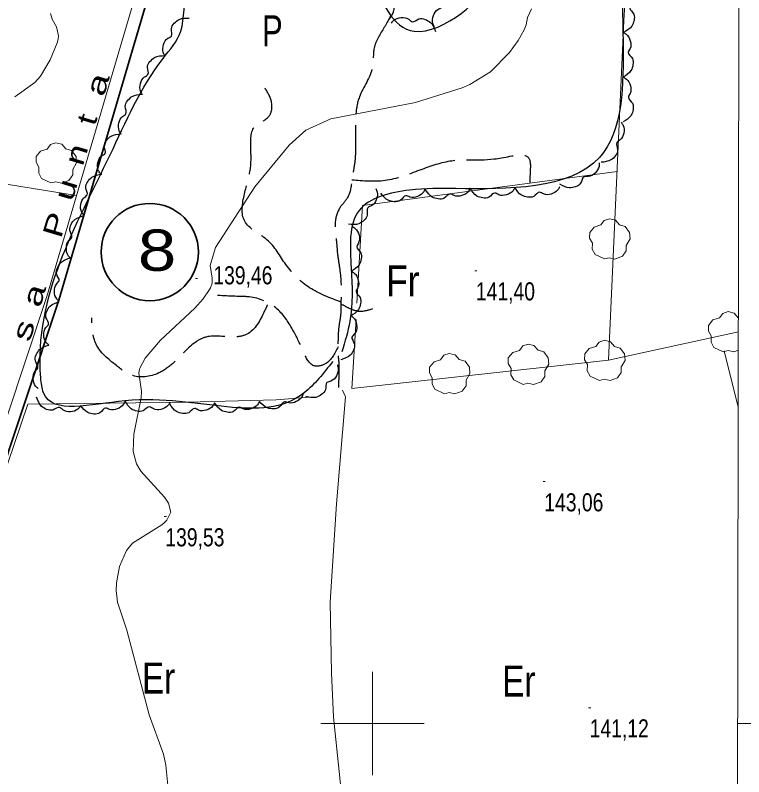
# Model space of a CAD drawing. Extents: x 483843 to 488449, y 4381269 to 4384483.
# Drawn here: x 487326.9 to 487679.8, y 4383474.2 to 4383843 of the extents above; entities that cross this region are included whole.
import ezdxf
from ezdxf.enums import TextEntityAlignment as Align

# ---------------------------------------------------------------- set-up
doc = ezdxf.new("R2010")
doc.units = 0
doc.header["$LTSCALE"] = 3.8
doc.linetypes.add('LONG_DASHED', pattern=[7.5, 6, -1.5])
for name, color, linetype, lineweight in [('1', 7, 'Continuous', 13), ('13', 7, 'Continuous', 35), ('27', 7, 'Continuous', 25), ('29', 7, 'Continuous', 13), ('38', 7, 'Continuous', 25), ('51', 7, 'Continuous', 13), ('6', 7, 'Continuous', 35), ('7', 7, 'Continuous', 13), ('9', 7, 'Continuous', 13)]:
    doc.layers.add(name, color=color, linetype=linetype, lineweight=lineweight)
doc.layers.add('31', color=7, linetype='Continuous')
doc.layers.add('5', color=7, linetype='Continuous')

msp = doc.modelspace()

# ---------------------------------------------------------------- linework, layer by layer
at = {"layer": '1'}
for p, q in [((487500, 4383525), (487500, 4383475)), ((487475, 4383500), (487525, 4383500)), ((487676.94, 4383500), (487747.35, 4383500))]:
    msp.add_line(p, q, dxfattribs=at)
msp.add_lwpolyline([(484100.5, 4384135.8), (487678, 4384129), (487674.1, 4381816.7), (484095.6, 4381823.6)], close=True, dxfattribs=at)
at = {"layer": '27'}
for points in [[(487480.78, 4383675.34), (487466.96, 4383660.21), (487380.11, 4383656.26), (487340.64, 4383660.21), (487339.32, 4383667.45), (487372.88, 4383775.35), (487398.54, 4383822.06), (487407.09, 4383835.22), (487411.04, 4383855.62), (487418.93, 4383863.51), (487499.86, 4383858.91), (487507.75, 4383844.43), (487520.25, 4383835.22), (487552.49, 4383856.93), (487526.17, 4383861.54), (487518.28, 4383875.36), (487551.18, 4383874.7), (487561.7, 4383881.28), (487551.83, 4383894.44), (487523.54, 4383888.51), (487511.04, 4383898.38), (487511.7, 4383916.81), (487504.46, 4383923.38), (487492.62, 4383912.2), (487422.22, 4383911.54), (487414.98, 4383942.46), (487426.17, 4383977.33), (487432.75, 4384004.31), (487446.57, 4384016.15), (487455.12, 4384015.49), (487461.04, 4383991.81), (487480.78, 4383982.6), (487489.33, 4383987.2), (487485.38, 4384009.57), (487466.3, 4384031.29), (487457.75, 4384079.97), (487466.3, 4384109.58), (487464.99, 4384121.42), (487438.67, 4384125.37)], [(487627.86, 4383963.16), (487632.22, 4383953.27), (487625.09, 4383901.15), (487621.38, 4383830.14), (487609.92, 4383774.03), (487540.44, 4383759.04), (487517.85, 4383758.31), (487493.54, 4383748.45), (487489.69, 4383720.6), (487489.02, 4383694.79), (487485.19, 4383680.06)], [(487500.34, 4383861.19), (487502.09, 4383860.87), (487505.03, 4383858.47), (487506.19, 4383854.97), (487506.01, 4383852.92), (487508.87, 4383850.82), (487510.17, 4383848.13), (487510.23, 4383845.1), (487507.76, 4383840.8)], [(487529.95, 4383837.43), (487529.21, 4383839.04), (487529.49, 4383842.83), (487531.69, 4383845.79), (487533.47, 4383846.81), (487533.54, 4383850.38), (487535, 4383852.98), (487537.44, 4383854.77), (487542.38, 4383855.22)], [(487622.73, 4383856.38), (487624.21, 4383855.4), (487625.98, 4383852.04), (487625.68, 4383848.36), (487624.72, 4383846.55), (487626.53, 4383843.49), (487626.68, 4383840.51), (487625.55, 4383837.71), (487621.6, 4383834.71)], [(487399.4, 4383823.43), (487398.61, 4383825.02), (487398.77, 4383828.81), (487400.87, 4383831.84), (487402.62, 4383832.92), (487402.58, 4383836.48), (487403.96, 4383839.13), (487406.34, 4383840.99), (487411.26, 4383841.6)], [(487509.18, 4383839.21), (487510.35, 4383840.55), (487513.91, 4383841.85), (487517.52, 4383841.06), (487519.19, 4383839.86), (487522.47, 4383841.25), (487525.44, 4383840.99), (487528.07, 4383839.51), (487530.51, 4383835.19)], [(487621.37, 4383834.71), (487622.9, 4383833.81), (487624.85, 4383830.56), (487624.75, 4383826.87), (487623.88, 4383825.01), (487625.86, 4383822.05), (487626.17, 4383819.08), (487625.19, 4383816.22), (487621.41, 4383813.01)], [(487388.58, 4383804.62), (487387.7, 4383806.16), (487387.63, 4383809.95), (487389.55, 4383813.1), (487391.23, 4383814.29), (487390.99, 4383817.83), (487392.2, 4383820.56), (487394.47, 4383822.56), (487399.35, 4383823.46)], [(487621.42, 4383813.01), (487622.96, 4383812.11), (487624.9, 4383808.86), (487624.8, 4383805.17), (487623.94, 4383803.31), (487625.91, 4383800.35), (487626.22, 4383797.38), (487625.25, 4383794.52), (487621.47, 4383791.31)], [(487378.26, 4383785.53), (487377.33, 4383787.04), (487377.13, 4383790.83), (487378.95, 4383794.04), (487380.59, 4383795.28), (487380.23, 4383798.82), (487381.36, 4383801.59), (487383.56, 4383803.66), (487388.4, 4383804.72)], [(487620.48, 4383791.15), (487621.44, 4383789.66), (487621.7, 4383785.87), (487619.94, 4383782.63), (487618.33, 4383781.36), (487618.75, 4383777.83), (487617.68, 4383775.04), (487615.52, 4383772.93), (487610.69, 4383771.78)], [(487368.12, 4383766.35), (487367.19, 4383767.86), (487367, 4383771.64), (487368.82, 4383774.86), (487370.46, 4383776.09), (487370.1, 4383779.63), (487371.22, 4383782.4), (487373.42, 4383784.47), (487378.27, 4383785.53)], [(487609.8, 4383771.58), (487609.75, 4383769.81), (487607.81, 4383766.55), (487604.51, 4383764.88), (487602.46, 4383764.76), (487600.81, 4383761.61), (487598.34, 4383759.93), (487595.36, 4383759.42), (487590.74, 4383761.23)], [(487360.21, 4383746.09), (487359.16, 4383747.53), (487358.68, 4383751.29), (487360.25, 4383754.63), (487361.78, 4383755.99), (487361.15, 4383759.49), (487362.06, 4383762.34), (487364.09, 4383764.57), (487368.84, 4383766)], [(487547.27, 4383759.22), (487546.42, 4383757.67), (487543.21, 4383755.64), (487539.52, 4383755.65), (487537.63, 4383756.47), (487534.73, 4383754.43), (487531.77, 4383754.05), (487528.88, 4383754.95), (487525.58, 4383758.65)], [(487568.97, 4383759.56), (487568.1, 4383758.02), (487564.88, 4383756.02), (487561.19, 4383756.06), (487559.31, 4383756.9), (487556.39, 4383754.87), (487553.42, 4383754.52), (487550.54, 4383755.45), (487547.28, 4383759.18)], [(487590.67, 4383759.96), (487589.8, 4383758.42), (487586.57, 4383756.42), (487582.88, 4383756.46), (487581.01, 4383757.3), (487578.08, 4383755.27), (487575.12, 4383754.92), (487572.24, 4383755.84), (487568.97, 4383759.57)], [(487501.59, 4383759.03), (487502.27, 4383757.39), (487501.84, 4383753.62), (487499.51, 4383750.75), (487497.69, 4383749.8), (487497.47, 4383746.25), (487495.91, 4383743.7), (487493.4, 4383742.02), (487488.44, 4383741.77)], [(487525.54, 4383759.16), (487524.82, 4383757.54), (487521.79, 4383755.26), (487518.11, 4383754.96), (487516.17, 4383755.62), (487513.44, 4383753.33), (487510.52, 4383752.71), (487507.57, 4383753.37), (487503.97, 4383756.78)], [(487353.7, 4383725.38), (487352.52, 4383726.71), (487351.7, 4383730.41), (487352.96, 4383733.88), (487354.36, 4383735.38), (487353.42, 4383738.81), (487354.06, 4383741.72), (487355.88, 4383744.13), (487360.48, 4383745.99)], [(487490.08, 4383740.72), (487491.59, 4383739.79), (487493.47, 4383736.5), (487493.29, 4383732.81), (487492.38, 4383730.97), (487494.29, 4383727.97), (487494.54, 4383725), (487493.5, 4383722.15), (487489.65, 4383719.03)], [(487348.29, 4383704.37), (487347.02, 4383705.61), (487345.91, 4383709.23), (487346.88, 4383712.79), (487348.17, 4383714.39), (487346.95, 4383717.73), (487347.36, 4383720.69), (487348.99, 4383723.24), (487353.43, 4383725.45)], [(487489.67, 4383719.03), (487491.19, 4383718.11), (487493.09, 4383714.82), (487492.93, 4383711.14), (487492.04, 4383709.29), (487493.97, 4383706.3), (487494.23, 4383703.33), (487493.21, 4383700.48), (487489.38, 4383697.33)], [(487343.17, 4383683.28), (487341.89, 4383684.52), (487340.78, 4383688.15), (487341.76, 4383691.71), (487343.04, 4383693.31), (487341.83, 4383696.65), (487342.24, 4383699.61), (487343.87, 4383702.15), (487348.3, 4383704.37)], [(487490, 4383697.19), (487491.27, 4383695.94), (487492.36, 4383692.31), (487491.35, 4383688.76), (487490.05, 4383687.17), (487491.24, 4383683.81), (487490.81, 4383680.86), (487489.16, 4383678.33), (487484.71, 4383676.15)], [(487338.04, 4383662.2), (487336.77, 4383663.43), (487335.65, 4383667.06), (487336.63, 4383670.62), (487337.92, 4383672.22), (487336.7, 4383675.56), (487337.11, 4383678.52), (487338.74, 4383681.07), (487343.18, 4383683.28)], [(487482.98, 4383673.75), (487483.43, 4383672.03), (487482.51, 4383668.35), (487479.84, 4383665.81), (487477.91, 4383665.1), (487477.22, 4383661.61), (487475.34, 4383659.29), (487472.63, 4383657.95), (487467.69, 4383658.35)], [(487466.48, 4383660.12), (487465.89, 4383658.44), (487463.07, 4383655.91), (487459.43, 4383655.3), (487457.44, 4383655.8), (487454.91, 4383653.29), (487452.06, 4383652.42), (487449.06, 4383652.83), (487445.19, 4383655.93)], [(487358.46, 4383653.5), (487357.26, 4383652.19), (487353.66, 4383650.98), (487350.08, 4383651.87), (487348.45, 4383653.11), (487345.14, 4383651.81), (487342.17, 4383652.15), (487339.58, 4383653.71), (487337.25, 4383658.09)], [(487380.12, 4383656.26), (487379.39, 4383654.65), (487376.35, 4383652.37), (487372.67, 4383652.1), (487370.73, 4383652.77), (487367.99, 4383650.5), (487365.07, 4383649.89), (487362.12, 4383650.56), (487358.54, 4383654)], [(487401.81, 4383655.45), (487400.85, 4383653.95), (487397.52, 4383652.13), (487393.84, 4383652.38), (487392.01, 4383653.32), (487388.98, 4383651.46), (487386, 4383651.28), (487383.18, 4383652.36), (487380.12, 4383656.27)], [(487445.19, 4383655.93), (487444.33, 4383654.38), (487441.13, 4383652.35), (487437.43, 4383652.36), (487435.55, 4383653.18), (487432.65, 4383651.13), (487429.69, 4383650.74), (487426.8, 4383651.64), (487423.5, 4383655.35)], [(487423.5, 4383655.34), (487422.64, 4383653.78), (487419.43, 4383651.75), (487415.74, 4383651.76), (487413.86, 4383652.58), (487410.96, 4383650.53), (487407.99, 4383650.15), (487405.11, 4383651.05), (487401.81, 4383654.75)]]:
    msp.add_spline(points, degree=3, dxfattribs=at)
at = {"layer": '29'}
for points in [[(487344.27, 4383761.78), (487339.73, 4383763.9), (487338.32, 4383766.44), (487338.42, 4383769.42), (487337.05, 4383771.83), (487337.09, 4383774.58), (487339.25, 4383777.18), (487342.44, 4383778.18), (487344.09, 4383780.37), (487346.66, 4383781.2), (487349.52, 4383780.55), (487351.47, 4383778.28), (487354.28, 4383777.46), (487356.41, 4383774.61), (487356.65, 4383771.48), (487354.77, 4383768.33), (487354.77, 4383765.65), (487352.95, 4383763.04), (487349.33, 4383761.7), (487346.56, 4383762.33)], [(487612.38, 4383725.02), (487607.84, 4383727.14), (487606.43, 4383729.68), (487606.53, 4383732.66), (487605.16, 4383735.07), (487605.2, 4383737.82), (487607.36, 4383740.42), (487610.55, 4383741.42), (487612.2, 4383743.61), (487614.77, 4383744.44), (487617.63, 4383743.79), (487619.58, 4383741.52), (487622.39, 4383740.7), (487624.52, 4383737.85), (487624.76, 4383734.72), (487622.88, 4383731.57), (487622.88, 4383728.89), (487621.06, 4383726.28), (487617.44, 4383724.94), (487614.67, 4383725.57)], [(487609.98, 4383666.15), (487605.44, 4383668.27), (487604.03, 4383670.81), (487604.13, 4383673.79), (487602.76, 4383676.2), (487602.8, 4383678.95), (487604.96, 4383681.55), (487608.15, 4383682.55), (487609.8, 4383684.74), (487612.37, 4383685.57), (487615.23, 4383684.92), (487617.18, 4383682.65), (487619.99, 4383681.83), (487622.12, 4383678.98), (487622.36, 4383675.85), (487620.48, 4383672.7), (487620.48, 4383670.02), (487618.66, 4383667.41), (487615.04, 4383666.07), (487612.27, 4383666.7)], [(487572.97, 4383664.25), (487568.43, 4383666.37), (487567.02, 4383668.91), (487567.12, 4383671.89), (487565.75, 4383674.3), (487565.79, 4383677.05), (487567.95, 4383679.65), (487571.14, 4383680.65), (487572.79, 4383682.84), (487575.36, 4383683.67), (487578.22, 4383683.02), (487580.17, 4383680.75), (487582.98, 4383679.93), (487585.11, 4383677.08), (487585.35, 4383673.95), (487583.47, 4383670.8), (487583.47, 4383668.12), (487581.65, 4383665.51), (487578.03, 4383664.17), (487575.26, 4383664.8)], [(487534.81, 4383659.73), (487530.27, 4383661.85), (487528.86, 4383664.39), (487528.96, 4383667.37), (487527.59, 4383669.78), (487527.63, 4383672.53), (487529.79, 4383675.13), (487532.98, 4383676.13), (487534.63, 4383678.32), (487537.2, 4383679.15), (487540.06, 4383678.5), (487542.01, 4383676.23), (487544.82, 4383675.41), (487546.95, 4383672.56), (487547.19, 4383669.43), (487545.31, 4383666.28), (487545.31, 4383663.6), (487543.49, 4383660.99), (487539.87, 4383659.65), (487537.1, 4383660.28)]]:
    msp.add_lwpolyline(points, close=True, dxfattribs=at)
for points in [[(487669.93, 4383680.03), (487665.39, 4383682.15), (487663.98, 4383684.69), (487664.08, 4383687.67), (487662.71, 4383690.08), (487662.75, 4383692.83), (487664.91, 4383695.43), (487668.1, 4383696.43), (487669.75, 4383698.62), (487672.32, 4383699.45), (487675.18, 4383698.8), (487677.13, 4383696.53), (487677.27, 4383696.49)], [(487677.24, 4383680.78), (487674.99, 4383679.95), (487672.22, 4383680.58), (487669.93, 4383680.03)]]:
    msp.add_lwpolyline(points, dxfattribs=at)
at = {"layer": '38', "linetype": 'LONG_DASHED'}
for points in [[(487547.94, 4384004.45), (487546.84, 4383996.36), (487544.14, 4383990.85), (487540.52, 4383984.6), (487537.59, 4383978.94), (487535.45, 4383976.34), (487532.24, 4383972.48), (487529.36, 4383965.02), (487527.29, 4383956.57), (487525, 4383954.2), (487521.79, 4383949.82), (487517.48, 4383942.61), (487516.44, 4383937.97), (487516.39, 4383934.37), (487516.63, 4383924.76), (487517.21, 4383918.22), (487516.95, 4383910.27), (487515.82, 4383905.11), (487514.29, 4383897.85), (487513.09, 4383892.24), (487510.94, 4383883.87), (487510.93, 4383872.69), (487511.18, 4383863.68), (487510.93, 4383856.86), (487510.78, 4383852.06), (487508.39, 4383842.04), (487502.85, 4383832.36), (487500.82, 4383827.14), (487500.01, 4383817.85), (487493.66, 4383803.45), (487491.87, 4383794.33), (487491.75, 4383785.4), (487491.79, 4383778.12), (487491.4, 4383771.75), (487490.08, 4383763.59), (487487.93, 4383754.76), (487484.11, 4383749.64), (487481.9, 4383742.02), (487482.53, 4383733.61), (487483.04, 4383727.52), (487484.06, 4383720.53), (487484.66, 4383714.74), (487484.73, 4383704.31), (487484.48, 4383697.33), (487483.74, 4383692.47), (487483.37, 4383688.05), (487483.28, 4383681.22), (487483.38, 4383677.77), (487483.64, 4383674.91), (487483.72, 4383670.26), (487483.46, 4383662.76)], [(487484.73, 4383704.11), (487469.52, 4383711.06), (487458.05, 4383722.25), (487448.84, 4383734.31), (487438.09, 4383743.25), (487437.98, 4383756.45), (487440.86, 4383768.72), (487441.07, 4383778.32), (487443.25, 4383789.39), (487449.77, 4383793.95), (487451.21, 4383800.16), (487447.94, 4383807.71)], [(487490.03, 4383763.37), (487506.06, 4383763.06), (487523.09, 4383768.14), (487538.46, 4383772.57), (487562.49, 4383773.88), (487575.77, 4383773.76), (487576.35, 4383766.78), (487576.2, 4383762.05)], [(487483.31, 4383682.43), (487477.1, 4383674.18), (487471.61, 4383673.28), (487466.6, 4383679.96), (487461.72, 4383690.08), (487453.84, 4383700.7), (487440.27, 4383706.6), (487435.24, 4383706.82), (487419.28, 4383707.8)], [(487449.13, 4383702.75), (487447.75, 4383699.81), (487439.11, 4383688.53), (487433.16, 4383687.19), (487419.43, 4383687.16), (487414.59, 4383684.9), (487404.33, 4383675.37), (487397.28, 4383670.14), (487383.89, 4383668.46), (487376.01, 4383673.3), (487366.1, 4383683.72), (487364.04, 4383696.43)], [(487484.7, 4383703.27), (487488.96, 4383701.02), (487493.07, 4383699.76), (487500.22, 4383700.94)]]:
    msp.add_spline(points, degree=3, dxfattribs=at)
at = {"layer": '51'}
for p, q in [((487125.08, 4383793.54), (487356.7, 4383755.63)), ((487670.26, 4383680.42), (487677.2, 4383653.16))]:
    msp.add_line(p, q, dxfattribs=at)
for points in [[(487311.13, 4384128.8), (487313.22, 4384102.05), (487318.45, 4384028.52), (487318.49, 4384024.64), (487320.8, 4384019.34), (487325.68, 4384016.3), (487425.67, 4383991.92), (487425.79, 4383991.71), (487425.84, 4383989.32), (487416.6, 4383959.24), (487342.3, 4383706.72), (487293.32, 4383559.7), (487280.1, 4383521.5)], [(487614.29, 4383675.89), (487621.82, 4383840.41), (487626.24, 4383912.98)], [(487618.48, 4383767.37), (487495.23, 4383750.91), (487492.48, 4383703.6)], [(487677.26, 4383689.66), (487614.29, 4383675.89), (487490.06, 4383662.29), (487492.01, 4383695.6)], [(487485.47, 4383661.38), (487486.85, 4383658.21), (487482.58, 4383606.34), (487479.5, 4383558.74), (487480.21, 4383524.51), (487481.1, 4383503.11), (487484.66, 4383469), (487487.84, 4383428.66), (487488.54, 4383404.33), (487488.99, 4383393.67), (487464.06, 4383398.08), (487395.78, 4383403.34), (487322.51, 4383406.49), (487271.69, 4383415.32), (487253.66, 4383419.33), (487288, 4383522.24), (487332.97, 4383654.63), (487360.36, 4383654.92), (487410.35, 4383655.55), (487453.29, 4383656.74), (487469.36, 4383658.01)]]:
    msp.add_lwpolyline(points, dxfattribs=at)
at = {"layer": '6'}
msp.add_lwpolyline([(487422.32, 4383957.52), (487348.01, 4383704.94), (487298.99, 4383557.78), (487262.98, 4383453.83), (487243.49, 4383397.09), (487215.9, 4383314.87), (487186.11, 4383226.43), (487182.63, 4383217.34), (487180.29, 4383212.75), (487175.73, 4383208.4), (487171.21, 4383207.02), (487166.04, 4383206.21), (487156.02, 4383207.28), (487132.44, 4383211.07), (487105.23, 4383213.77), (487076.64, 4383213.95), (487066.01, 4383213.3), (487054.41, 4383209.96), (487044.4, 4383205.38), (487035.65, 4383198.23), (487028.06, 4383187.44)], dxfattribs=at)
msp.add_circle((487392.1, 4383728.32), 23.55, dxfattribs=at)
at = {"layer": '7'}
for p, q in [((487549.58, 4383719.28), (487550.58, 4383719.28)), ((487414.23, 4383715.44), (487415.23, 4383715.44)), ((487582.71, 4383617.13), (487583.71, 4383617.13)), ((487399.15, 4383600.18), (487400.15, 4383600.18)), ((487604.7, 4383507.64), (487605.7, 4383507.64))]:
    msp.add_line(p, q, dxfattribs=at)
at = {"layer": '9'}
for points in [[(487575.1, 4383841.83), (487576.95, 4383846.09)], [(487343.98, 4383843.78), (487344.88, 4383841.12), (487346.94, 4383837.39), (487347.89, 4383833.09), (487347.67, 4383831.46), (487347.23, 4383829.63), (487343.89, 4383821.47), (487339.12, 4383813.55), (487336.44, 4383810.44), (487326.77, 4383803.47)], [(487402.86, 4383450.84), (487399.91, 4383479.9), (487398.75, 4383485.18), (487391.84, 4383504.24), (487380.97, 4383545.25), (487376.43, 4383558.82), (487375.79, 4383564.37), (487376.02, 4383568.1), (487377.49, 4383576.01), (487380.87, 4383583.77), (487382.25, 4383585.6), (487383.82, 4383587.29), (487397.99, 4383596.24), (487399.32, 4383597.34), (487400.42, 4383598.43), (487402.29, 4383602.35), (487401.11, 4383606.78), (487399.22, 4383609.69), (487387.77, 4383622.26), (487385.71, 4383625.71), (487384.04, 4383631.72), (487384.44, 4383640.05), (487387.98, 4383657.65), (487388.17, 4383661.03), (487386.82, 4383669.59), (487387.02, 4383670.79), (487387.38, 4383672.04), (487389.92, 4383676.91), (487397.37, 4383685.64), (487413.97, 4383701.11), (487418, 4383705.7), (487421.11, 4383710.19), (487421.54, 4383710.98), (487422.39, 4383713.27), (487422.41, 4383715.7), (487421.34, 4383721.8), (487423.98, 4383730.57), (487443.01, 4383759.87), (487459.67, 4383780.14), (487467.67, 4383787.3), (487479.89, 4383792.88), (487520.83, 4383800.73), (487543.46, 4383807.8), (487547.18, 4383809.42), (487557.08, 4383815.53), (487566.43, 4383825.01), (487570.61, 4383830.76), (487573.41, 4383835.88), (487574.38, 4383838.28), (487575.1, 4383841.83)]]:
    msp.add_lwpolyline(points, dxfattribs=at)

# ---------------------------------------------------------------- texts
at = {"layer": '13', "width": 1.25}
msp.add_text('8', height=20, dxfattribs=at).set_placement((487386.35, 4383719.24))
at = {"layer": '31'}
for s, width, p in [('P', 0.75, (487451.5, 4383827.94)), ('Fr', 0.85, (487514.68, 4383706.83)), ('Er', 0.8, (487396.39, 4383514.5)), ('Er', 0.8, (487570.89, 4383513.08))]:
    msp.add_text(s, height=15, dxfattribs=dict(at, width=width)).set_placement(p, align=Align.CENTER)
at = {"layer": '5'}
for s, width, p in [('a', 1.5, (487371.3, 4383808.19)), ('t', 1.35, (487366.19, 4383791.21)), ('n', 1.4, (487361.05, 4383774.19)), ('u', 1.4, (487355.91, 4383757.17)), ('P', 1.4, (487350.79, 4383740.13)), ('a', 1.5, (487340.51, 4383706.06)), ('s', 1.55, (487335.37, 4383689.04))]:
    msp.add_text(s, height=9.49, rotation=73.218, dxfattribs=dict(at, width=width)).set_placement(p, align=Align.CENTER)
at = {"layer": '7', "width": 0.8}
for s, p in [('139,46', (487422.9, 4383712.69)), ('141,40', (487550.08, 4383704.91)), ('143,06', (487583.21, 4383602.76)), ('139,53', (487399.65, 4383585.81)), ('141,12', (487605.2, 4383493.27))]:
    msp.add_text(s, height=8.75, dxfattribs=at).set_placement(p)

doc.saveas('drawing.dxf')
